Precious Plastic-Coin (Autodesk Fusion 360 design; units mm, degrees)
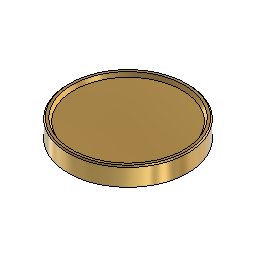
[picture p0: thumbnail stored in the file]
sketch "Sketch1" plane through (0, 0, 0) normal (0, 0, 1) x axis (1, 0, 0)
  circle C1 centre (0, 0) radius 10.175
  point P1 (0, 0)
  point P2 (0, 0)
  coincident P1 P2
  dimension "d1" diameter C1 = 20.35
extrude "Extrude1" new body sketch "Sketch1" along normal blind 3.14
sketch "Sketch2" plane through (0, 0, 3.14) normal (0, 0, 1) x axis (-1, 0, 0)
  circle C1 centre (0, 0) radius 10.175
  circle C2 centre (0, 0) radius 9.55
  point P1 (0, 0)
  point P3 (0, 0)
  coincident P1 P3
  dimension "d4" diameter C2 = 19.1
extrude "Extrude2" cut sketch "Sketch2" profile of C2 against normal blind 0.6
chamfer "Chamfer2" distance 0.2 Rotate Angle 45
draft "Draft1" Angle1 30 Angle2 0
